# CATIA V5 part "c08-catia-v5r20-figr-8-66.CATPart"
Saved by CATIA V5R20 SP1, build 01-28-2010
Part number: Part1
Bounding box of the stored display mesh (mm): x -53.439 to 53.439, y -63.41 to 63.41, z -17.5 to 17.5
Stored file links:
  D:\v5_r20\psrt_files_downloaded\c08-catia-v5r20-prt\c08-catia-v5r20-figr-8-66.CATPart
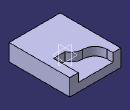
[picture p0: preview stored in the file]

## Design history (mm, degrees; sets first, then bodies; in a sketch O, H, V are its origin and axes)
Body1 (main body)
  Sketch1 on xy-plane, origin (0, 0, 0), H (1, 0, 0), V (0, 1, 0)
    line L1 (-53.4395, 63.4095) -> (53.4395, 63.4095)
    line L2 (53.4395, 63.4095) -> (53.4395, -63.4095)
    line L3 (53.4395, -63.4095) -> (-53.4395, -63.4095)
    line L4 (-53.4395, -63.4095) -> (-53.4395, 63.4095)
    axis line L5 (53.4395, -63.4095) -> (-53.4395, 63.4095)
    horizontal: L1 H, L3 H
    vertical: L2 V, L4 V
    midpoint: O L5
  Pad1: profile Sketch1, direction (0, 0, 1), length 17.5, mirrored extent
  Body2
    Sketch2 on xy-plane, origin (0, 0, 0), H (1, 0, 0), V (0, 1, 0)
      line L1 (-36.9238, 103.6333) -> (-36.9238, 51.4035)
      arc A1 centre (-11.4307, 51.4035) radius 25.4931 from (-36.9238, 51.4035) to (-11.4307, 25.9104) ccw
      arc A2 centre (-11.4307, 0.4172) radius 25.4931 from (-11.4307, 25.9104) to (11.4981, 11.5602) cw
      line L2 (11.4981, 11.5602) -> (35.6176, 11.5602)
      line L3 (35.6176, 11.5602) -> (35.6176, 103.6333)
      line L4 (35.6176, 103.6333) -> (-36.9238, 103.6333)
      vertical: L1 V, L3 V
      tangency: A1 L1, A2 L1, A2 A1
      horizontal: L2 H, L4 H
    Pad2: profile Sketch2, direction (0, 0, 1), length 34.5
  Remove1: tool Body2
